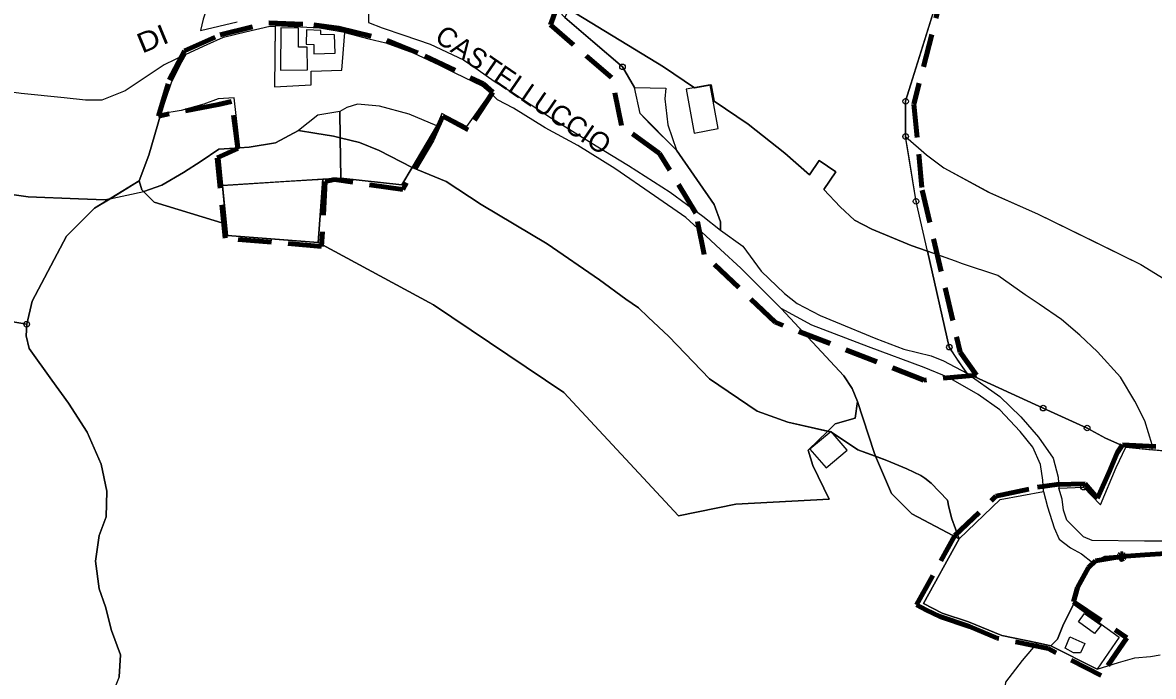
# Model space of a CAD drawing. Extents: x 652791 to 656927, y 889884 to 892405.
# Drawn here: x 655580 to 656147, y 891468 to 891796 of the extents above; entities that cross this region are included whole.
import ezdxf
from ezdxf.enums import TextEntityAlignment as Align

# ---------------------------------------------------------------- set-up
doc = ezdxf.new("R2010")
doc.units = 0
doc.header["$LTSCALE"] = 5.6
doc.header["$PDMODE"] = 32
doc.header["$PDSIZE"] = 2.8
doc.linetypes.add('MEDIUM_DASHED', pattern=[4.5, 3, -1.5])
for name, color, linetype, lineweight in [('11', 7, 'Continuous', 25), ('12', 7, 'Continuous', 25), ('14', 7, 'Continuous', 25), ('23', 7, 'Continuous', 25), ('3', 7, 'Continuous', 25), ('30', 7, 'Continuous', 25), ('33', 7, 'Continuous', 25), ('35', 7, 'Continuous', 25), ('4', 7, 'Continuous', 25), ('55', 7, 'Continuous', 25), ('6', 7, 'Continuous', 25), ('7', 7, 'MEDIUM_DASHED', 100), ('9', 7, 'Continuous', 25)]:
    doc.layers.add(name, color=color, linetype=linetype, lineweight=lineweight)
doc.layers.add('60', color=7, linetype='Continuous')

msp = doc.modelspace()

# ---------------------------------------------------------------- linework, layer by layer
at = {"layer": '11'}
for p, q in [((655775.65, 891723.07), (655787.92, 891743.85)), ((655770.51, 891714.36), (655775.65, 891723.07))]:
    msp.add_line(p, q, dxfattribs=at)
for points in [[(655787.92, 891743.85), (655774.16, 891749.84), (655759.2, 891753.83), (655748.23, 891754.83), (655742.84, 891753.03), (655739.35, 891751.06), (655739.55, 891737.95)], [(655739.55, 891737.95), (655749.21, 891735.64), (655759.14, 891731.56), (655775.65, 891723.07)], [(655775.65, 891723.07), (655759.14, 891731.56), (655749.21, 891735.64), (655739.55, 891737.95), (655739.87, 891717.77), (655770.51, 891714.36)]]:
    msp.add_lwpolyline(points, dxfattribs=at)
at = {"layer": '12'}
msp.add_lwpolyline([(655887.11, 891763.14), (655902.81, 891762.74), (655902.36, 891757.5), (655903.81, 891744.41), (655908.14, 891731.75), (655889.85, 891750.11)], close=True, dxfattribs=at)
at = {"layer": '14'}
for points in [[(655739.55, 891737.95), (655739.35, 891751.06), (655728.31, 891749.29), (655718.71, 891741.57), (655707.19, 891735.45), (655693.85, 891733.26)], [(655739.35, 891751.06), (655728.31, 891749.29), (655718.71, 891741.57), (655726.88, 891740.22), (655736.16, 891738.76)], [(655736.16, 891738.76), (655739.55, 891737.95), (655739.35, 891751.06)], [(655693.85, 891733.26), (655689.18, 891732.88), (655679.25, 891727.7), (655680.56, 891714.07), (655711.36, 891715.99), (655739.87, 891717.77), (655739.55, 891737.95)], [(655739.55, 891737.95), (655736.16, 891738.76), (655726.88, 891740.22), (655718.71, 891741.57), (655707.19, 891735.45), (655693.85, 891733.26)], [(655711.36, 891715.99), (655739.87, 891717.77), (655739.55, 891737.95)], [(655693.85, 891733.26), (655689.18, 891732.88), (655679.25, 891727.7), (655682.43, 891694.65)], [(655682.43, 891694.65), (655680.56, 891714.07), (655711.36, 891715.99)]]:
    msp.add_lwpolyline(points, dxfattribs=at)
at = {"layer": '23'}
msp.add_lwpolyline([(655680.56, 891714.07), (655682.98, 891688.96), (655728.52, 891685.4), (655730.87, 891717.2)], close=True, dxfattribs=at)
at = {"layer": '3'}
for points in [[(656118.99, 891471.57), (656095.78, 891483.3), (656099.14, 891486.61), (656101.8, 891493.4), (656107.17, 891504.21), (656130.01, 891487.68)], [(656109.65, 891495.35), (656112.6, 891499.55), (656121.04, 891493.64), (656117.62, 891489.51)], [(656105.28, 891487.85), (656112.84, 891484.54), (656110.71, 891479.82), (656107.17, 891479.76), (656103.04, 891482.18)]]:
    msp.add_lwpolyline(points, close=True, dxfattribs=at)
at = {"layer": '30'}
for p, q in [((655775.65, 891723.07), (655792.69, 891716.09)), ((655640.98, 891710.97), (655641.05, 891711.03)), ((655851.67, 891610.21), (655909.11, 891548.53)), ((656146.57, 891581.6), (656146.52, 891583.98))]:
    msp.add_line(p, q, dxfattribs=at)
for points in [[(655754.3, 891845.65), (655753.43, 891833.77), (655753.71, 891795.7), (655760.59, 891793.02)], [(655930.23, 891691.47), (655930.27, 891695.83), (655926.99, 891704.53), (655908.14, 891731.75), (655894.99, 891744.76), (655889.85, 891750.11), (655887.11, 891763.14), (655881.08, 891773.51), (655866.28, 891786.27), (655852.15, 891798.25)], [(655760.59, 891793.02), (655771.5, 891789.38), (655784.68, 891784.84), (655801.35, 891776.95), (655808.78, 891771.95), (655816.66, 891766.34)], [(655624.23, 891707.41), (655638.75, 891716.34), (655643.58, 891729.3), (655649.69, 891749.91), (655649.69, 891749.91), (655654.92, 891765.7), (655659.31, 891774.47), (655662.32, 891779.79), (655651.25, 891774.53), (655631.73, 891761.54), (655620.08, 891756.78), (655611.93, 891756.78), (655601.23, 891757.96), (655579.7, 891760.18), (655562.48, 891762.4), (655415.63, 891768.33), (655402.54, 891769.12), (655403.75, 891739.36), (655413.39, 891718.75)], [(655816.66, 891766.34), (655825.15, 891761.18), (655845.46, 891747.84), (655867.89, 891733.89), (655884.11, 891724.03), (655905.02, 891710.69), (655921.39, 891698.71), (655930.15, 891691.57), (655930.23, 891691.47)], [(655814.94, 891760.42), (655802.95, 891743.58), (655790.52, 891750.05), (655787.92, 891743.85), (655775.65, 891723.07)], [(655930.14, 891681.93), (655922.91, 891688.86), (655912.9, 891697.95), (655897.14, 891708.87), (655877.29, 891722.52), (655858.65, 891734.04), (655842.28, 891742.84), (655826.37, 891752.85), (655818.49, 891756.94), (655814.94, 891760.42)], [(655689.18, 891732.88), (655686.48, 891757.95), (655678.39, 891757.37), (655671.21, 891754.75), (655659.82, 891751.55), (655649.69, 891749.91), (655643.58, 891729.3), (655638.75, 891716.34), (655640.11, 891711.82), (655640.98, 891710.97), (655641.05, 891711.03)], [(655689.18, 891732.93), (655686.48, 891757.95), (655678.39, 891757.37), (655671.21, 891754.75), (655659.82, 891751.55), (655649.69, 891749.91), (655643.58, 891729.3), (655638.75, 891716.34), (655640.11, 891711.82), (655640.98, 891710.97), (655641.05, 891711.03)], [(655689.18, 891732.93), (655686.48, 891757.95), (655678.39, 891757.37), (655671.21, 891754.75), (655659.82, 891751.55), (655649.69, 891749.91), (655643.58, 891729.3), (655638.75, 891716.34), (655640.11, 891711.82), (655640.98, 891710.97), (655641.05, 891711.03)], [(655689.18, 891732.93), (655686.48, 891757.95), (655678.39, 891757.37), (655671.21, 891754.75), (655659.82, 891751.55), (655649.69, 891749.91), (655643.58, 891729.3), (655638.75, 891716.34), (655640.11, 891711.82), (655640.98, 891710.97)], [(656033.93, 891681.09), (656028.23, 891706.07), (656024.27, 891730.81), (656023, 891738.57), (656033.49, 891729.45), (656042.16, 891722.94), (656065.31, 891710.28), (656089.17, 891699.79), (656118.1, 891685.67), (656140.89, 891674.46), (656167.75, 891657.93), (656167.75, 891649.15), (656170.42, 891639.61), (656174.23, 891627.77), (656175.38, 891617.47), (656177.69, 891580.17), (656168.2, 891579.6), (656146.57, 891581.6)], [(655669.78, 891726.16), (655678.74, 891732.21), (655689.18, 891732.93)], [(655669.78, 891726.16), (655678.74, 891732.21), (655689.18, 891732.93)], [(655669.78, 891726.16), (655678.74, 891732.21), (655689.18, 891732.93)], [(655689.18, 891732.93), (655678.74, 891732.21), (655669.78, 891726.16)], [(655669.78, 891726.16), (655678.74, 891732.21), (655689.18, 891732.88)], [(655682.43, 891694.65), (655679.25, 891727.7), (655689.18, 891732.88)], [(655641.05, 891711.03), (655650.1, 891714.15), (655660.98, 891720.45), (655669.78, 891726.16)], [(655641.05, 891711.03), (655650.1, 891714.15), (655660.98, 891720.45), (655669.78, 891726.16)], [(655641.05, 891711.03), (655650.1, 891714.15), (655660.98, 891720.45), (655669.78, 891726.16)], [(655641.05, 891711.03), (655650.1, 891714.15), (655660.98, 891720.45), (655669.78, 891726.16)], [(655669.78, 891726.16), (655660.98, 891720.45), (655650.1, 891714.15), (655641.05, 891711.03)], [(655775.65, 891723.07), (655770.51, 891714.36), (655739.87, 891717.77), (655730.87, 891717.2), (655728.52, 891685.4)], [(655963.97, 891595.48), (655948.53, 891600.89), (655924.6, 891617.19), (655904.23, 891638.28), (655893.99, 891647.96), (655889.04, 891652.71), (655882.74, 891657.12), (655869.55, 891666.72), (655843.24, 891684.83), (655810.27, 891704.44), (655792.69, 891716.09), (655775.65, 891723.07)], [(655413.39, 891718.75), (655414.72, 891718.64), (655448.2, 891717.07), (655501.55, 891714.9), (655520.78, 891714.9), (655533.84, 891714.12), (655553.45, 891712.46), (655583.07, 891708.37), (655608.33, 891707.35), (655621.67, 891706.86), (655624.23, 891707.41)], [(655624.23, 891707.41), (655621.67, 891706.86), (655608.33, 891707.35), (655583.07, 891708.37), (655553.45, 891712.46), (655533.84, 891714.12), (655520.78, 891714.9), (655501.55, 891714.9), (655448.2, 891717.07), (655414.72, 891718.64), (655413.39, 891718.75)], [(655792.69, 891716.09), (655810.27, 891704.44), (655843.24, 891684.83), (655869.55, 891666.72), (655882.74, 891657.12), (655889.04, 891652.71), (655893.99, 891647.96), (655904.23, 891638.28), (655924.6, 891617.19), (655948.53, 891600.89), (655963.97, 891595.48), (655983.92, 891590.89)], [(655640.98, 891710.97), (655646.33, 891705.74), (655682.43, 891694.65)], [(655502.53, 891652.82), (655513.97, 891654.03), (655558.88, 891647.07), (655572.43, 891646.12), (655582.42, 891644.49), (655585.17, 891656.03), (655602.35, 891688.57), (655616.37, 891702.58), (655624.23, 891707.41)], [(655728.52, 891685.4), (655786.39, 891654.24), (655851.67, 891610.21)], [(655983.92, 891590.89), (655987.7, 891594.55), (655997.77, 891597.37), (655998.84, 891605.69), (655996.21, 891612.22), (655992.09, 891618.54), (655960.62, 891652.29), (655940.34, 891672.63), (655930.14, 891681.93)], [(656146.52, 891583.98), (656142.88, 891596.13), (656137.97, 891605.94), (656130.72, 891618.03), (656119.2, 891630.57), (656110.31, 891639.06), (656101.22, 891646.79), (656090.02, 891654.51), (656082.94, 891659.24), (656069.26, 891668.87), (656051.54, 891674.78), (656047.97, 891676.14), (656033.93, 891681.09)], [(656033.93, 891681.09), (656044.9, 891632.99), (656049.41, 891625.93), (656053.68, 891619.89), (656091.93, 891602.45)], [(656146.52, 891583.98), (656142.88, 891596.13), (656137.97, 891605.94), (656130.72, 891618.03), (656119.2, 891630.57), (656110.31, 891639.06), (656101.22, 891646.79), (656090.02, 891654.51), (656082.94, 891659.24), (656069.26, 891668.87), (656051.54, 891674.78), (656047.97, 891676.14), (656033.93, 891681.09)], [(656091.93, 891602.45), (656113.98, 891592.47), (656123.15, 891587.4), (656133.47, 891582.81), (656146.57, 891581.6), (656146.52, 891583.98)], [(655909.11, 891548.53), (655937.84, 891554.35), (655984.75, 891556.73), (655976.43, 891573.76), (655974.18, 891581.45), (655983.92, 891590.89), (655963.97, 891595.48)]]:
    msp.add_lwpolyline(points, dxfattribs=at)
at = {"layer": '33'}
for p, q in [((656023, 891738.57), (656023, 891756.2)), ((656028.23, 891706.07), (656023, 891738.57)), ((656044.9, 891632.99), (656033.93, 891681.09))]:
    msp.add_line(p, q, dxfattribs=at)
for points in [[(656023, 891756.2), (656043.33, 891821.39), (656047.32, 891834.46), (656040.98, 891832.9), (655998.19, 891828.4), (655989.69, 891854.52)], [(655962.52, 891730.25), (655943.99, 891744.83), (655926.98, 891756.35), (655925.47, 891764.52), (655917.18, 891762.98), (655901.55, 891773.56), (655854.22, 891802.39), (655852.15, 891798.25), (655866.28, 891786.27), (655881.08, 891773.51)], [(655854.22, 891802.39), (655901.55, 891773.56), (655917.18, 891762.98), (655925.47, 891764.52), (655926.98, 891756.35), (655943.99, 891744.83), (655962.52, 891730.25)], [(655881.08, 891773.51), (655887.11, 891763.14), (655902.81, 891762.74)], [(655902.81, 891762.74), (655902.36, 891757.5), (655903.81, 891744.41), (655908.14, 891731.75), (655926.99, 891704.53), (655930.26, 891695.83), (655930.15, 891691.57), (655941.34, 891683.65), (655950.64, 891671.07)], [(656033.93, 891681.09), (656025.72, 891683.99), (656006.08, 891692.06), (655997.29, 891696.67), (655990.13, 891703.4), (655981.99, 891712.07), (655987.95, 891720.84), (655979.67, 891726.48), (655974.8, 891719.3), (655962.52, 891730.25)], [(655962.52, 891730.25), (655974.8, 891719.3), (655979.67, 891726.48), (655987.95, 891720.84), (655981.99, 891712.07), (655990.13, 891703.4), (655997.29, 891696.67), (656006.08, 891692.06), (656025.72, 891683.99), (656033.93, 891681.09), (656028.23, 891706.07)], [(655950.64, 891671.07), (655962.36, 891659.87), (655968.56, 891654.87), (655980.09, 891648.84), (655987.84, 891645.74), (656007.99, 891637.3), (656022.12, 891631.96), (656035.72, 891628.68), (656041.92, 891626.1), (656053.68, 891619.89), (656044.9, 891632.99)]]:
    msp.add_lwpolyline(points, dxfattribs=at)
for p in [(655881.08, 891773.51), (656023, 891756.2), (656023, 891738.57), (656028.23, 891706.07), (656044.9, 891632.99)]:
    msp.add_point(p, dxfattribs=at)
at = {"layer": '35'}
for p, q in [((656091.93, 891602.45), (656053.68, 891619.89)), ((656113.98, 891592.47), (656091.93, 891602.45))]:
    msp.add_line(p, q, dxfattribs=at)
for points in [[(655700.24, 891847.42), (655699.56, 891846.42), (655693.7, 891838.71), (655685.03, 891829.36), (655679.08, 891820.43), (655673.63, 891805.75), (655670.94, 891797.41), (655669.46, 891791.77), (655687.95, 891796.1)], [(656047.32, 891834.46), (656023, 891756.2), (656023, 891738.57), (656033.49, 891729.45), (656042.16, 891722.94), (656064.51, 891710.71), (656089.17, 891699.79), (656140.89, 891674.46), (656167.75, 891657.93), (656167.75, 891657.93), (656166.96, 891671.83), (656165.46, 891680.68), (656162.03, 891693.05), (656158.68, 891704.42), (656156.3, 891713.28), (656153.25, 891723.59), (656154.2, 891735.29), (656156.98, 891739.83), (656160.57, 891743.21), (656170.25, 891748.49), (656177.5, 891754.21), (656187.83, 891763.23), (656212.68, 891789), (656236.47, 891823.03)], [(655682.98, 891688.96), (655682.43, 891694.65), (655646.33, 891705.74), (655640.11, 891711.82), (655638.75, 891716.34), (655616.37, 891702.58), (655602.35, 891688.57), (655585.17, 891656.03)], [(655786.39, 891654.24), (655728.52, 891685.4), (655700.38, 891687.6), (655682.98, 891688.96)], [(655585.17, 891656.03), (655585.17, 891656.03), (655582.42, 891644.49)], [(655999.02, 891581.54), (655985.86, 891590.44), (655983.92, 891590.89), (655974.18, 891581.45), (655976.43, 891573.76), (655984.75, 891556.73), (655937.84, 891554.35), (655909.11, 891548.53), (655851.67, 891610.21), (655786.39, 891654.24)], [(656092.04, 891560.61), (656091.83, 891566.28), (656090.56, 891574.24), (656086.74, 891582.84), (656080.37, 891590.8), (656070.19, 891601.63), (656059.37, 891609.27), (656044.41, 891617.87), (656032.35, 891622.8), (656004.42, 891633.19), (655976.02, 891644.02), (655960.62, 891652.29), (655992.09, 891618.54)], [(655628.74, 891467.78), (655629.38, 891478.72), (655624.88, 891490.95), (655621.98, 891502.86), (655618.76, 891511.87), (655616.83, 891525.71), (655618.76, 891538.59), (655622.3, 891547.92), (655622.62, 891560.8), (655619.73, 891574.32), (655612.65, 891590.41), (655603.32, 891604.9), (655594.96, 891616.49), (655583.7, 891632.26), (655582.09, 891638.7), (655582.42, 891644.49), (655572.43, 891646.12)], [(655582.42, 891644.49), (655582.09, 891638.7), (655583.7, 891632.26), (655594.96, 891616.49), (655603.32, 891604.9), (655612.65, 891590.41), (655619.73, 891574.32), (655622.62, 891560.8), (655622.3, 891547.92), (655618.76, 891538.59), (655616.83, 891525.71), (655618.76, 891511.87), (655621.98, 891502.86), (655624.88, 891490.95), (655629.38, 891478.72), (655628.74, 891467.78), (655623.59, 891454.9), (655619.73, 891442.67), (655614.99, 891436)], [(655992.09, 891618.54), (655996.21, 891612.22), (655998.84, 891605.69), (656007.16, 891580.22), (656007.97, 891578.31)], [(656053.68, 891619.89), (656070.19, 891608.32), (656080.69, 891598.13), (656089.6, 891587.94), (656096.92, 891577.43), (656099.47, 891567.87), (656099.86, 891562.27), (656112.2, 891562.81)], [(655999.02, 891581.54), (656007.97, 891578.31), (656007.16, 891580.22), (655998.84, 891605.69), (655997.77, 891597.37), (655987.7, 891594.55), (655983.92, 891590.89)], [(655983.92, 891590.89), (655985.86, 891590.44), (655999.02, 891581.54)], [(656112.2, 891562.81), (656120.71, 891554.02), (656128.51, 891572.64), (656133.47, 891582.81), (656123.15, 891587.4), (656113.98, 891592.47)], [(656078.47, 891422.3), (656074.29, 891435.57), (656072.29, 891443.27), (656071.65, 891452.77), (656073.24, 891465.01), (656081.57, 891475.88), (656089.03, 891484.77), (656071.19, 891488.48), (656054.45, 891495.4), (656041.28, 891499.66), (656031.95, 891504.45), (656049.79, 891536.92), (656026.15, 891549.44), (656015.9, 891559.7), (656007.97, 891578.31), (655999.02, 891581.54)], [(656007.97, 891578.31), (656013.65, 891576.27), (656023.55, 891572.06), (656030.63, 891568.7), (656032.6, 891567.36), (656035.8, 891564.83), (656044.01, 891556.26), (656044.67, 891552.8), (656046.16, 891546.93), (656049.79, 891536.92), (656070.37, 891556.62), (656092.04, 891560.61)], [(656046.16, 891546.93), (656044.67, 891552.8), (656044.01, 891556.26), (656035.8, 891564.83), (656032.6, 891567.36), (656030.63, 891568.7), (656023.55, 891572.06), (656013.65, 891576.27), (656007.97, 891578.31), (656015.9, 891559.7), (656026.15, 891549.44)], [(656026.15, 891549.44), (656049.79, 891536.92), (656046.16, 891546.93)], [(656166.51, 891527.84), (656154.23, 891530.47), (656122.64, 891528.13), (656116.65, 891525.08)], [(656116.65, 891525.08), (656109.5, 891512.33), (656107.17, 891504.21), (656130.01, 891487.68), (656118.99, 891471.57)], [(656422.77, 891464.02), (656413.94, 891456.5), (656226.36, 891386.67), (656205.54, 891383.87), (656165.13, 891384.18), (656146.48, 891382.01), (656108.81, 891370.86), (656095.2, 891368.25), (656091.47, 891367.73), (656081.59, 891365.81), (656087.34, 891377.65), (656090.3, 891385.37), (656088.48, 891398.33), (656078.47, 891422.3), (656074.29, 891435.57), (656072.29, 891443.27), (656071.65, 891452.77), (656073.24, 891465.01), (656081.57, 891475.88), (656089.03, 891484.77), (656095.78, 891483.3), (656118.99, 891471.57)], [(656118.99, 891471.57), (656129.71, 891474.95), (656137.93, 891477.26), (656145.68, 891477.91), (656150.56, 891478.82)], [(656118.99, 891471.57), (656129.71, 891474.95), (656137.93, 891477.26), (656145.68, 891477.91), (656150.56, 891478.82)]]:
    msp.add_lwpolyline(points, dxfattribs=at)
for p in [(655582.42, 891644.49), (656091.93, 891602.45), (656113.98, 891592.47), (656112.2, 891562.81)]:
    msp.add_point(p, dxfattribs=at)
at = {"layer": '4'}
for points in [[(655706.87, 891794.07), (655706.6, 891763.54), (655724.96, 891764.4), (655724.96, 891771.27), (655740.41, 891771.81), (655741.93, 891790.72), (655729.26, 891792.82)], [(655709.82, 891793.07), (655709.61, 891771.81), (655723.13, 891771.91), (655723.03, 891783.41), (655718.73, 891783.41), (655718.62, 891792.86)], [(655722.72, 891791.99), (655722.51, 891784.9), (655726.37, 891784.68), (655726.37, 891780.06), (655737.1, 891780.28), (655736.68, 891789.52), (655729.91, 891789.73), (655729.8, 891791.77)]]:
    msp.add_lwpolyline(points, close=True, dxfattribs=at)
at = {"layer": '55'}
for points in [[(655962.52, 891730.25), (655943.99, 891744.83), (655926.98, 891756.35), (655925.47, 891764.52), (655917.18, 891762.98), (655901.55, 891773.56), (655854.22, 891802.39), (655852.15, 891798.25), (655839.18, 891812.21), (655826.35, 891820.69), (655804.95, 891830.79), (655790.33, 891836.18), (655772.53, 891841.86), (655756.37, 891845.22)], [(655693.85, 891733.26), (655707.19, 891735.45), (655718.71, 891741.57), (655726.88, 891740.22), (655736.16, 891738.76), (655749.21, 891735.64), (655759.14, 891731.56), (655775.65, 891723.07), (655792.69, 891716.09)], [(655669.78, 891726.16), (655678.74, 891732.21), (655693.85, 891733.26)], [(655402.51, 891719.63), (655414.72, 891718.64), (655448.2, 891717.07), (655501.55, 891714.9), (655520.78, 891714.9), (655533.84, 891714.12), (655553.45, 891712.46), (655583.07, 891708.37), (655608.33, 891707.35), (655621.67, 891706.86), (655641.05, 891711.03), (655650.1, 891714.15), (655660.98, 891720.45), (655669.78, 891726.16)], [(656047.97, 891676.14), (656025.72, 891683.99), (656006.08, 891692.06), (655997.29, 891696.67), (655990.13, 891703.4), (655981.99, 891712.07), (655987.95, 891720.84), (655979.67, 891726.48), (655974.8, 891719.3), (655962.52, 891730.25)], [(655792.69, 891716.09), (655810.27, 891704.44), (655843.24, 891684.83), (655869.55, 891666.72), (655882.74, 891657.12), (655889.04, 891652.71), (655893.99, 891647.96), (655904.23, 891638.28), (655924.6, 891617.19), (655948.53, 891600.89), (655963.97, 891595.48)], [(656146.52, 891583.98), (656142.88, 891596.13), (656137.97, 891605.94), (656130.72, 891618.03), (656119.2, 891630.57), (656110.31, 891639.06), (656101.22, 891646.79), (656090.02, 891654.51), (656082.94, 891659.24), (656069.26, 891668.87), (656051.54, 891674.78), (656047.97, 891676.14)], [(655963.97, 891595.48), (655985.86, 891590.44), (655999.02, 891581.54), (656013.65, 891576.27), (656023.55, 891572.06), (656030.63, 891568.7), (656032.6, 891567.36), (656035.8, 891564.83), (656044.01, 891556.26), (656044.67, 891552.8), (656046.16, 891546.93)], [(656168.2, 891579.6), (656146.57, 891581.6), (656146.52, 891583.98)], [(656046.16, 891546.93), (656049.79, 891536.92), (656031.95, 891504.45), (656041.28, 891499.66), (656054.45, 891495.4), (656071.19, 891488.48), (656089.03, 891484.77), (656095.78, 891483.3), (656118.99, 891471.57)], [(656118.99, 891471.57), (656129.71, 891474.95), (656137.93, 891477.26), (656145.68, 891477.91), (656150.56, 891478.82)]]:
    msp.add_lwpolyline(points, dxfattribs=at)
at = {"layer": '6'}
for points in [[(655912.91, 891762.26), (655916.97, 891740.29), (655929.02, 891742.52), (655924.96, 891764.49)], [(655985.61, 891590.68), (655975.03, 891581.82), (655983.18, 891572.5), (655993.76, 891581.36)]]:
    msp.add_lwpolyline(points, close=True, dxfattribs=at)
at = {"layer": '7'}
msp.add_line((656131.29, 891528.04), (656118.15, 891525.93), dxfattribs=at)
for points in [[(656048.66, 891838.5), (656027.14, 891754.83), (656031.28, 891711.75), (656050.32, 891630.56), (656058.6, 891618.96), (656032.11, 891616.48), (655957.59, 891645.47), (655921.99, 891679.44), (655917.85, 891700.15), (655899.63, 891729.98), (655880.59, 891744.06), (655875.62, 891768.08), (655844.99, 891794.59), (655859.89, 891836.84)], [(656118.15, 891525.93), (656114.62, 891522.58), (656109.14, 891512.56), (656107.09, 891505.36), (656133.83, 891487.28), (656120.98, 891468.41), (656094.49, 891481.91), (656068.83, 891487.14), (656055, 891492.91), (656040.08, 891497.96), (656033.5, 891501.15), (656028.52, 891503.81), (656047.69, 891538.55), (656068.27, 891558.25), (656089.16, 891562.75), (656098.81, 891564.24), (656112.92, 891564.48), (656119.11, 891557.3), (656125.29, 891571.17), (656129, 891580.08)], [(656129, 891580.08), (656131.73, 891584.05), (656167.86, 891582.06), (656168.86, 891554.58), (656168.36, 891526.1), (656153.52, 891529.58), (656142.9, 891528.92), (656131.29, 891528.04)]]:
    msp.add_lwpolyline(points, dxfattribs=at)
msp.add_lwpolyline([(655648.52, 891748.84), (655653.82, 891766.91), (655661.52, 891781.52), (655679.31, 891789.49), (655704, 891795.6), (655726.3, 891794.53), (655738.78, 891792.94), (655762.94, 891786.83), (655781.99, 891778.99), (655811.14, 891765.12), (655816.12, 891760.85), (655803.74, 891741.85), (655791.06, 891748.76), (655785.72, 891736.97), (655770.88, 891711.94), (655736.65, 891716.98), (655732.1, 891715.97), (655730.19, 891683.52), (655681.86, 891687.55), (655677.84, 891727.85), (655688.3, 891732.6), (655685.04, 891756.05), (655678.52, 891754.69), (655653.85, 891749.87)], close=True, dxfattribs=at)
msp.add_point((656131.29, 891528.04), dxfattribs=at)
at = {"layer": '9'}
for points in [[(655689.18, 891732.88), (655686.48, 891757.95), (655678.39, 891757.37), (655671.21, 891754.75), (655659.82, 891751.55), (655649.69, 891749.91), (655654.92, 891765.7), (655659.31, 891774.47), (655662.32, 891779.79), (655672.89, 891784.69), (655681.12, 891788.41), (655692.1, 891791.07), (655704.32, 891793.8), (655706.87, 891793.83), (655706.6, 891763.54), (655724.96, 891764.4), (655724.96, 891771.27), (655740.41, 891771.81), (655741.93, 891790.72)], [(655741.93, 891790.72), (655753.95, 891787.46), (655762.51, 891785.57), (655776.06, 891780.58), (655789.08, 891774.49), (655797.07, 891770.45), (655810.53, 891764.01), (655810.51, 891764.06), (655814.94, 891760.42), (655802.95, 891743.58), (655790.52, 891750.05), (655787.92, 891743.85)], [(655787.92, 891743.85), (655774.16, 891749.84), (655759.2, 891753.83), (655748.23, 891754.83), (655742.84, 891753.03), (655739.35, 891751.06), (655728.31, 891749.29), (655718.71, 891741.57), (655707.19, 891735.45), (655693.85, 891733.26), (655689.18, 891732.88)], [(656099.86, 891562.27), (656112.2, 891562.81), (656120.71, 891554.02), (656128.51, 891572.64), (656133.47, 891582.81), (656168.2, 891579.6), (656168.12, 891556.06), (656168.45, 891532.73)], [(656168.45, 891532.73), (656162.02, 891534.55), (656154.23, 891535.73), (656142.71, 891535.73), (656116.47, 891536.07), (656112.24, 891537.93), (656103.77, 891546.23), (656102.08, 891551.32), (656101.4, 891556.74), (656099.86, 891562.27)], [(656116.64, 891525.08), (656109.5, 891512.33), (656107.17, 891504.21), (656101.8, 891493.4), (656099.14, 891486.61), (656095.78, 891483.3), (656089.03, 891484.77), (656071.19, 891488.48), (656054.45, 891495.4), (656041.28, 891499.66), (656031.95, 891504.45), (656049.79, 891536.92), (656070.37, 891556.62), (656092.04, 891560.61)], [(656092.04, 891560.61), (656094.12, 891553.01), (656097.51, 891542.51), (656100.05, 891536.75), (656105.64, 891532.34), (656111.22, 891529.46), (656116.64, 891525.08)]]:
    msp.add_lwpolyline(points, dxfattribs=at)

# ---------------------------------------------------------------- texts
at = {"layer": '60', "width": 1.15}
msp.add_text('DI', height=10, rotation=22.527, dxfattribs=at).set_placement((655647.39, 891783), align=Align.CENTER)
at = {"layer": '60'}
msp.add_text('CASTELLUCCIO', height=10, rotation=325.573, dxfattribs=at).set_placement((655828.58, 891757.86), align=Align.CENTER)

doc.saveas('drawing.dxf')
